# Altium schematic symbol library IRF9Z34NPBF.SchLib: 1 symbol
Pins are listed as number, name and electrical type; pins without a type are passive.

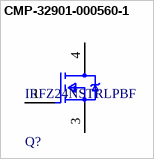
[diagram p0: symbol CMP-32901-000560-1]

## CMP-32901-000560-1
designator Q?, comment IRFZ24NSTRLPBF
MOSFET N-CH 55V 17A D2PAK; Element Configuration: Single; Turn-On Delay Time: 4.9ns; Power Dissipation: 45W; Gate to Source Voltage (Vgs): 20V; Input Capacitance: 370pF; Turn-Off Delay Time: 19ns; Max Power Dissipation: 3.8W; Drain to Source Resistance: 70mR
footprint FP-PG-TO263-3-MFG
pins: 1 GATE, 3 SOURCE, 4 DRAIN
